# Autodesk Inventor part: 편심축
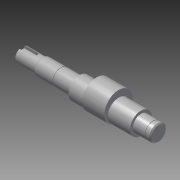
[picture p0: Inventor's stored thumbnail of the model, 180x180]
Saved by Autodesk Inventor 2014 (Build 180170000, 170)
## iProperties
Created: 2015-12
Part Number: 편심축
Material: 강철, 연강
Document SubType Name: Modeling
Designer: mduedu
Density: 7.86 g/cm^3
Appearance: Steel
Author: mduedu
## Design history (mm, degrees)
sketch "스케치1"
  geometry: L1 (-62.5, 0)-(62.5, 0); L2 (-62.5, 0)-(-62.5, 6.5); L3 (-62.5, 6.5)-(-43.5, 6.5); L4 (-43.5, 7)-(-42.634, 7.5); L5 (-42.634, 7.5)-(-9.5, 7.5); L6 (-9.5, 7.5)-(-9.5, 10); L7 (-9.5, 10)-(46.5, 10); L8 (46.5, 10)-(46.5, 7.5); L9 (46.5, 7.5)-(62.5, 7.5); L10 (62.5, 7.5)-(62.5, 0); L11 (-43.5, 6.5)-(-43.5, 7); 2 further points
  constraints: 22 end point, 6 parallel, 2 perpendicular, 1 coincident, 1 horizontal, 1 midpoint, 1 vertical
  dimensions: "d0" = 13 diameter of L3 L1; "d2" = 15 diameter of L5 L1; "d3" = 20 diameter of L7 L1; "d5" = 15 diameter of L9 L1; "d6" = 125 distance of L1.start L1.end; "d7" = 19 distance of L2.end L3.end; "d8" = 34 distance from line of L6 L3.end; "d9" = 56 distance of L6.end L7.end; "d41" = 14 diameter of L4.start L1; "d42" = 30 deg angle of L4 L3
revolve "회전1" sketch "스케치1" stored, may be unused: angle "d11" = 90 deg
node "작업 평면1"
sketch "스케치2"
  geometry: C1 r 13 at (0, 3); 1 further point
  constraints: 1 centre point, 1 vertical alignment
  dimensions: "d13" = 26 diameter of C1; "d14" = 3 distance of point (0, 0) C1.centre
extrude "돌출1" join sketch "스케치2" distance "d15" = 20; taper "d16" = 0 deg
node "작업 평면2"
sketch "스케치3"
  geometry: L1 (9.5, -2.5)-(-2.5, -2.5); L2 (-2.5, 2.5)-(9.5, 2.5); L3 (9.5, 2.5)-(9.5, -2.5); L4 (9.5, 6.5)-(9.5, -6.5) reference; A1 r 2.5 centre (-2.5, 0) between (-2.5, 2.5) and (-2.5, -2.5); 1 further point
  constraints: 6 end point, 2 point on circle, 2 tangent, 1 centre point, 1 collinear, 1 horizontal, 1 horizontal alignment, 1 parallel
  dimensions: "d17" = 5 distance of L2.end L1.start; "d19" = 12 distance from line of A1.centre L3
extrude "돌출2" cut sketch "스케치3" distance "d20" = 3; taper "d21" = 0 deg
chamfer "모따기1" distance "d22" = 1; stored, may be unused: second distance "d23" = 2, angle "d24" = 45 deg
fillet "모깎기1" dims "d25" = 3
sketch "스케치4"
  geometry: L1 (-9.5, -10)-(-9.5, 10) reference; L2 (-9.5, 0)-(0, 0); L3 (-26.65, 12.15)-(-25.5, 12.15); L4 (-25.5, 12.15)-(-25.5, 7.15); L5 (-25.5, 7.15)-(-26.65, 7.15); L6 (-26.65, 7.15)-(-26.65, 12.15); L7 (57.5, 12.15)-(58.65, 12.15); L8 (58.65, 12.15)-(58.65, 7.15); L9 (58.65, 7.15)-(57.5, 7.15); L10 (57.5, 7.15)-(57.5, 12.15); L11 (62.5, -7.5)-(62.5, 7.5) reference
  constraints: 18 end point, 4 parallel, 2 horizontal, 2 perpendicular, 1 midpoint
  dimensions: "d26" = 16 distance between parallel lines of L4 L1; "d27" = 1.15 distance of L3.start L3.end; "d28" = 14.3 diameter of L5 L2; "d29" = 5 distance of L3.end L4.end; "d30" = 1.15 distance of L7.start L7.end; "d31" = 5 distance of L7.end L8.end; "d32" = 5 distance between parallel lines of L10 L11; "d33" = 14.3 diameter of L9 L2
revolve "회전2" sketch "스케치4" stored, may be unused: angle "d34" = 90 deg
chamfer "모따기2" distance "d35" = 1; stored, may be unused: second distance "d36" = 2, angle "d37" = 45 deg
fillet "모깎기2" dims "d38" = 0.3
sketch "스케치5"
  geometry: 2 further points
  constraints: 1 coincident
sketch "스케치6"
  geometry: 1 further point
hole "구멍1" sketch "스케치6" at (2.5, -3.5) diameter "d43" = 4.917; stored, may be unused: countersink angle "d47" = 90 deg, drill point angle "d49" = 120 deg; dims "d44" = 14, "d45" = 4, "d46" = 2, "d48" = 17
node "솔리드1"
other parameters: "d12" = -15.5
